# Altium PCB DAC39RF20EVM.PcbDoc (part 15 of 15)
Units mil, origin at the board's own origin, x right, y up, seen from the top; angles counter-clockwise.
Board outline 6200 x 2716.54 mil, 16 copper layers (Top Layer, L2 GND, L3 PWR, L4 GND, L5 PWR, L6 GND, L7 SIG, L8 GND, L9 GND, L10 SIG, L11 GND, L12 PWR, L13 GND, L14 PWR, L15 GND, Bottom Layer), stack 76.97 mil thick; 766 components, 495 nets, 3414 pads, 2373 vias.
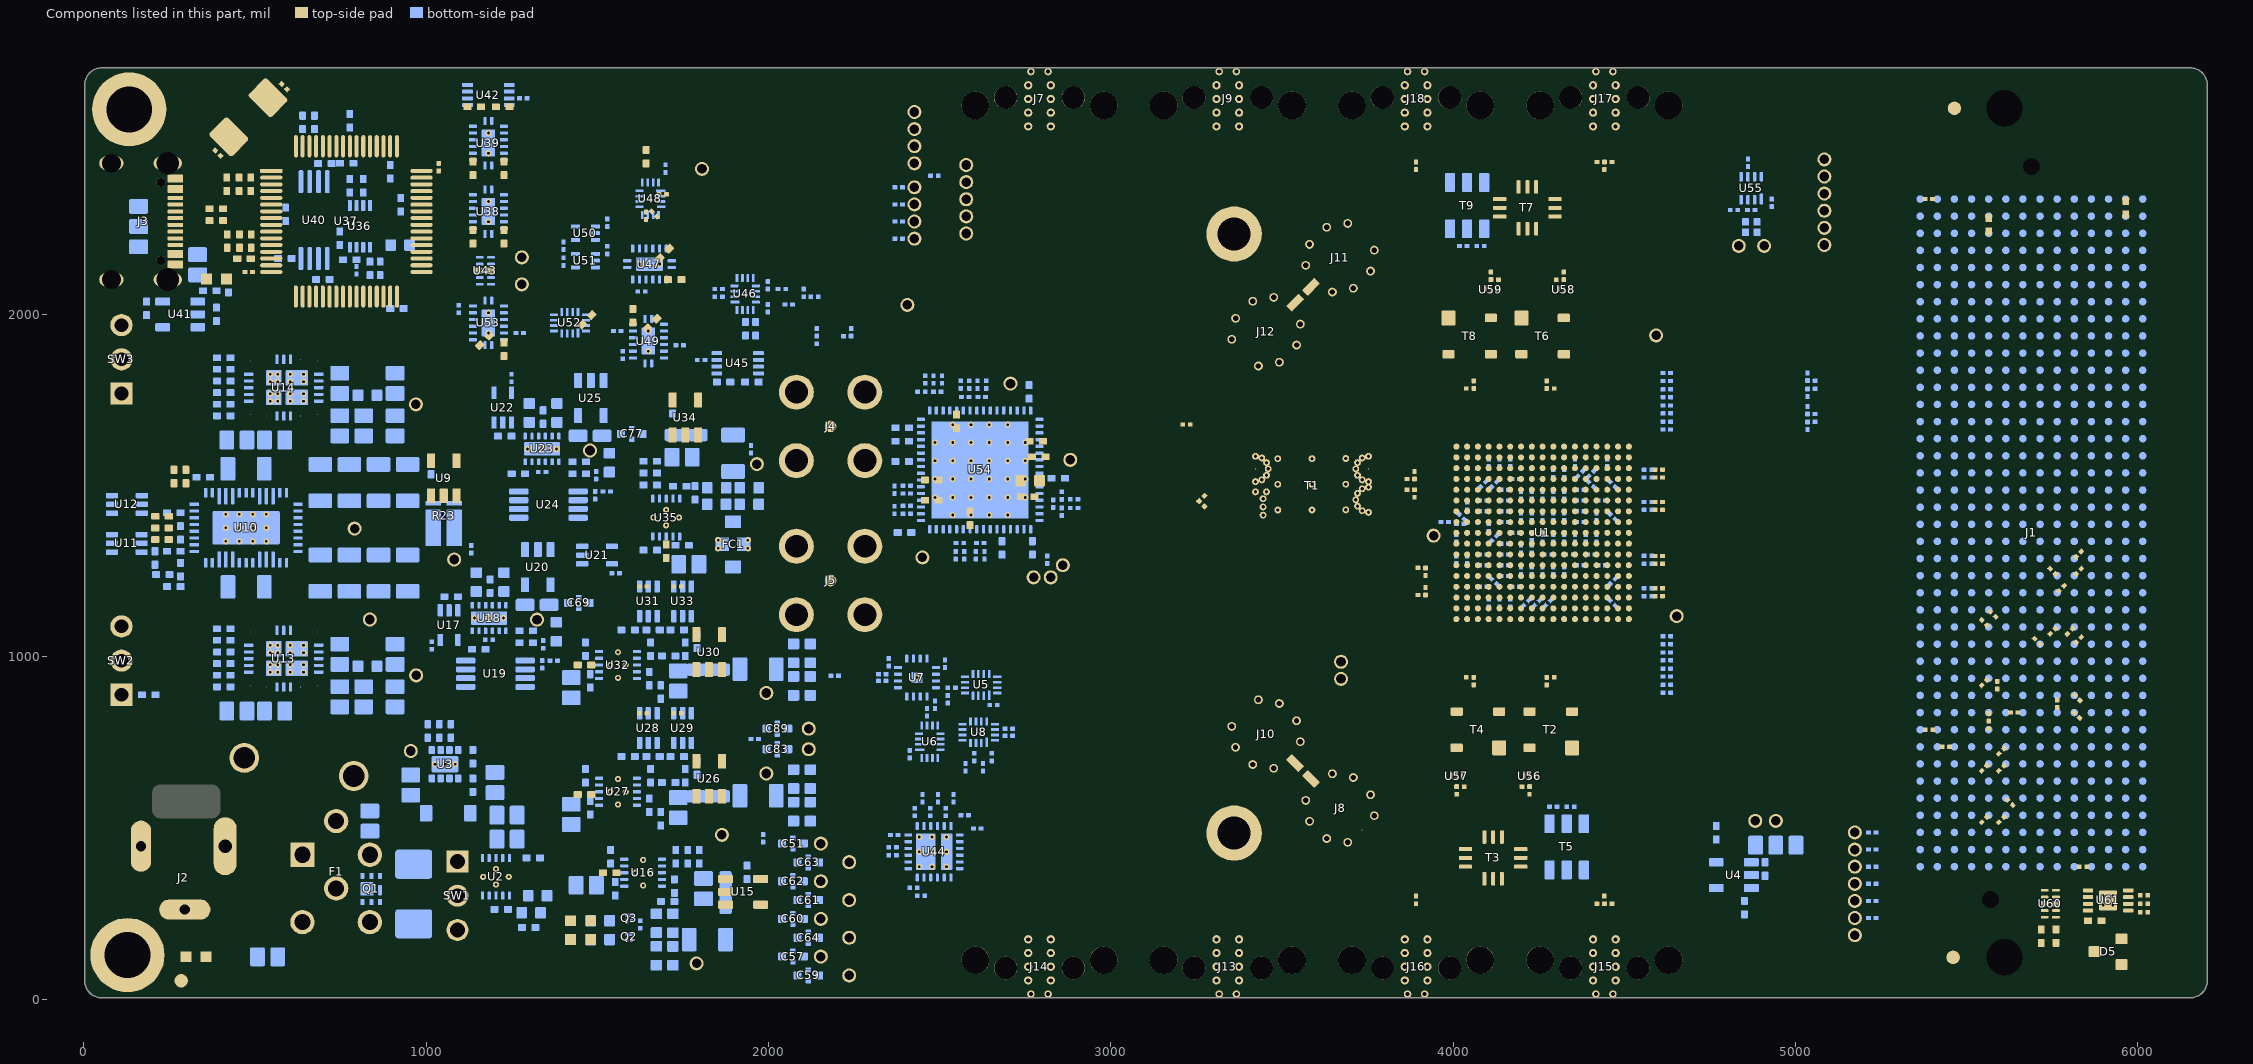
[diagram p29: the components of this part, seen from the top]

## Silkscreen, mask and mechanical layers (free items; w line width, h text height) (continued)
Drill Drawing:
  drawing of 189 lines, arcs and shapes, not listed
  text "Symbol" at 461.25,6525 h48
  text "Count" at 809.17,6525 h48
  text "Hole Size" at 1255.71,6525 h48
  text "Plated" at 2028.82,6525 h48
  text "Hole Type" at 2376.74,6525 h48
  text "Drill Layer Pair" at 2876.61,6525 h48
  text "Via/Pad" at 3882.98,6525 h48
  text "Pad Shape" at 4286.88,6525 h48
  text "Template" at 5020,6525 h48
  text "Description" at 6172.99,6525 h48
  text "Hole Tolerance (+)" at 6752.83,6525 h48
  text "Hole Tolerance (-)" at 7652.57,6525 h48
  text "1" at 809.17,6425 h40
  text "39.76mil (1.010mm)" at 1255.71,6425 h40
  text "PTH" at 2028.82,6425 h40
  text "Slot" at 2376.74,6425 h40
  text "Top Layer - Bottom Layer" at 2876.61,6425 h40
  text "Pad" at 3882.98,6425 h40
  text "Rounded" at 4286.88,6425 h40
  text "r430_170h101_356r85" at 5020,6425 h40
  text "2" at 809.17,6325 h40
  text "25.59mil (0.650mm)" at 1255.71,6325 h40
  text "NPTH" at 2028.82,6325 h40
  text "Round" at 2376.74,6325 h40
  text "Top Layer - Bottom Layer" at 2876.61,6325 h40
  text "Pad" at 3882.98,6325 h40
  text "Rounded" at 4286.88,6325 h40
  text "c65hn65m65p0" at 5020,6325 h40
  text "2" at 809.17,6225 h40
  text "29.92mil (0.760mm)" at 1255.71,6225 h40
  text "PTH" at 2028.82,6225 h40
  text "Slot" at 2376.74,6225 h40
  text "Top Layer - Bottom Layer" at 2876.61,6225 h40
  text "Pad" at 3882.98,6225 h40
  text "Rounded" at 4286.88,6225 h40
  text "r380_150h76_305r75" at 5020,6225 h40
  text "2" at 809.17,6125 h40
  text "50.00mil (1.270mm)" at 1255.71,6125 h40
  text "NPTH" at 2028.82,6125 h40
  text "Round" at 2376.74,6125 h40
  text "Top Layer - Bottom Layer" at 2876.61,6125 h40
  text "Pad" at 3882.98,6125 h40
  text "Rounded" at 4286.88,6125 h40
  text "c-127hn127" at 5020,6125 h40
  text "2" at 809.17,6025 h40
  text "55.12mil (1.400mm)" at 1255.71,6025 h40
  text "PTH" at 2028.82,6025 h40
  text "Slot" at 2376.74,6025 h40
  text "Top Layer - Bottom Layer" at 2876.61,6025 h40
  text "Pad" at 3882.98,6025 h40
  text "Rounded Rectangle" at 4286.88,6025 h40
  text "r100_180h140_60r50m100_180p0" at 5020,6025 h40
  text "A" at 439.56,6015.01 h44.44
  text "2" at 809.17,5925 h40
  text "63.00mil (1.600mm)" at 1255.71,5925 h40
  text "PTH" at 2028.82,5925 h40
  text "Round" at 2376.74,5925 h40
  text "Top Layer - Bottom Layer" at 2876.61,5925 h40
  text "Pad" at 3882.98,5925 h40
  text "Rounded" at 4286.88,5925 h40
  text "c221h160" at 5020,5925 h40
  text "2" at 809.17,5825 h40
  text "66.93mil (1.700mm)" at 1255.71,5825 h40
  text "PTH" at 2028.82,5825 h40
  text "Slot" at 2376.74,5825 h40
  text "Top Layer - Bottom Layer" at 2876.61,5825 h40
  text "Pad" at 3882.98,5825 h40
  text "Rounded Rectangle" at 4286.88,5825 h40
  text "r100_210h170_60r50m100_210p0" at 5020,5825 h40
  text "2" at 809.17,5725 h40
  text "96.46mil (2.450mm)" at 1255.71,5725 h40
  text "NPTH" at 2028.82,5725 h40
  text "Round" at 2376.74,5725 h40
  text "Top Layer - Bottom Layer" at 2876.61,5725 h40
  text "Pad" at 3882.98,5725 h40
  text "Rounded" at 4286.88,5725 h40
  text "c410hn245m410" at 5020,5725 h40
  text "H" at 439.56,5715.01 h44.44
  text "2" at 809.17,5625 h40
  text "105.91mil (2.690mm)" at 1255.71,5625 h40
  text "NPTH" at 2028.82,5625 h40
  text "Round" at 2376.74,5625 h40
  text "Top Layer - Bottom Layer" at 2876.61,5625 h40
  text "Pad" at 3882.98,5625 h40
  text "Rounded" at 4286.88,5625 h40
  text "c-127hn269" at 5020,5625 h40
  text "2" at 809.17,5525 h40
  text "133.86mil (3.400mm)" at 1255.71,5525 h40
  text "PTH" at 2028.82,5525 h40
  text "Round" at 2376.74,5525 h40
  text "Top Layer - Bottom Layer" at 2876.61,5525 h40
  text "Pad" at 3882.98,5525 h40
  text "Rounded" at 4286.88,5525 h40
  text "c550h340m550p0" at 5020,5525 h40
  text "3" at 809.17,5425 h40
  text "42.91mil (1.090mm)" at 1255.71,5425 h40
  text "PTH" at 2028.82,5425 h40
  text "Round" at 2376.74,5425 h40
  text "Top Layer - Bottom Layer" at 2876.61,5425 h40
  text "Pad" at 3882.98,5425 h40
  text "(Mixed)" at 4286.88,5425 h40
  text "(Mixed)" at 5020,5425 h40
  text "6" at 809.17,5325 h40
  text "40.00mil (1.016mm)" at 1255.71,5325 h40
  text "PTH" at 2028.82,5325 h40
  text "Round" at 2376.74,5325 h40
  text "Top Layer - Bottom Layer" at 2876.61,5325 h40
  text "Pad" at 3882.98,5325 h40
  text "(Mixed)" at 4286.88,5325 h40
  text "(Mixed)" at 5020,5325 h40
  text "6" at 809.17,5225 h40
  text "47.24mil (1.200mm)" at 1255.71,5225 h40
  text "PTH" at 2028.82,5225 h40
  text "Round" at 2376.74,5225 h40
  text "Top Layer - Bottom Layer" at 2876.61,5225 h40
  text "Pad" at 3882.98,5225 h40
  text "(Mixed)" at 4286.88,5225 h40
  text "(Mixed)" at 5020,5225 h40
  text "16" at 809.17,5125 h40
  text "81.00mil (2.057mm)" at 1255.71,5125 h40
  text "PTH" at 2028.82,5125 h40
  text "Round" at 2376.74,5125 h40
  text "Top Layer - Bottom Layer" at 2876.61,5125 h40
  text "Pad" at 3882.98,5125 h40
  text "Rounded" at 4286.88,5125 h40
  text "c206h206m286" at 5020,5125 h40
  text "G" at 439.56,5115.01 h44.44
  text "24" at 809.17,5025 h40
  text "66.93mil (1.700mm)" at 1255.71,5025 h40
  text "PTH" at 2028.82,5025 h40
  text "Round" at 2376.74,5025 h40
  text "Top Layer - Bottom Layer" at 2876.61,5025 h40
  text "Pad" at 3882.98,5025 h40
  text "Rounded" at 4286.88,5025 h40
  text "(Mixed)" at 5020,5025 h40
  text "B" at 439.56,5015.01 h44.44
  text "32" at 809.17,4925 h40
  text "15.75mil (0.400mm)" at 1255.71,4925 h40
  text "PTH" at 2028.82,4925 h40
  text "Round" at 2376.74,4925 h40
  text "Top Layer - Bottom Layer" at 2876.61,4925 h40
  text "Pad" at 3882.98,4925 h40
  text "Rounded" at 4286.88,4925 h40
  text "c65h40m0mx0" at 5020,4925 h40
  text "36" at 809.17,4825 h40
  text "10.00mil (0.254mm)" at 1255.71,4825 h40
  text "PTH" at 2028.82,4825 h40
  text "Round" at 2376.74,4825 h40
  text "Top Layer - Bottom Layer" at 2876.61,4825 h40
  text "(Mixed)" at 3882.98,4825 h40
  text "Rounded" at 4286.88,4825 h40
  text "(Mixed)" at 5020,4825 h40
  text "D" at 439.56,4815.01 h44.44
  text "68" at 809.17,4725 h40
  text "28.00mil (0.711mm)" at 1255.71,4725 h40
  text "PTH" at 2028.82,4725 h40
  text "Round" at 2376.74,4725 h40
  text "Top Layer - Bottom Layer" at 2876.61,4725 h40
  text "Pad" at 3882.98,4725 h40
  text "Rounded" at 4286.88,4725 h40
  text "c104h71" at 5020,4725 h40
  text "99" at 809.17,4625 h40
  text "12.00mil (0.305mm)" at 1255.71,4625 h40
  text "PTH" at 2028.82,4625 h40
  text "Round" at 2376.74,4625 h40
  text "Top Layer - Bottom Layer" at 2876.61,4625 h40
  text "(Mixed)" at 3882.98,4625 h40
  text "Rounded" at 4286.88,4625 h40
  text "(Mixed)" at 5020,4625 h40
  text "C" at 439.56,4615.01 h44.44
  text "130" at 809.17,4525 h40
  text "7.87mil (0.200mm)" at 1255.71,4525 h40
  text "PTH" at 2028.82,4525 h40
  text "Round" at 2376.74,4525 h40
  text "Top Layer - Bottom Layer" at 2876.61,4525 h40
  text "Pad" at 3882.98,4525 h40
  text "Rounded" at 4286.88,4525 h40
  text "(Mixed)" at 5020,4525 h40
  text "2356" at 809.17,4425 h40
  text "8.00mil (0.203mm)" at 1255.71,4425 h40
  text "PTH" at 2028.82,4425 h40
  text "Round" at 2376.74,4425 h40
  text "Top Layer - Bottom Layer" at 2876.61,4425 h40
  text "(Mixed)" at 3882.98,4425 h40
  text "Rounded" at 4286.88,4425 h40
  text "(Mixed)" at 5020,4425 h40
  text "2795 Total" at 809.17,4325 h40
  text "Slot definitions :" at 461.25,4221.68 h40
  text "Routed Path Length" at 1159.04,4221.68 h40
  text "= Calculated from tool start centre position to tool end centre position." at 1903.49,4221.68 h40
  text "Hole Length" at 1159.04,4148.37 h40
  text "= Routed Path Length + Tool Size = Slot length as defined in the PCB layout" at 1630.24,4148.37 h40
  text ".Layer_Name" at 579.59,-854.69 h60

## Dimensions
2.59,103.8 to 6202.59,103.8 on M2 Board Dimensions
102.59,2720.34 to 102.59,3.8 on M2 Board Dimensions
2.59,-396.2 to 1002.59,-396.2 on M2 Board Dimensions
